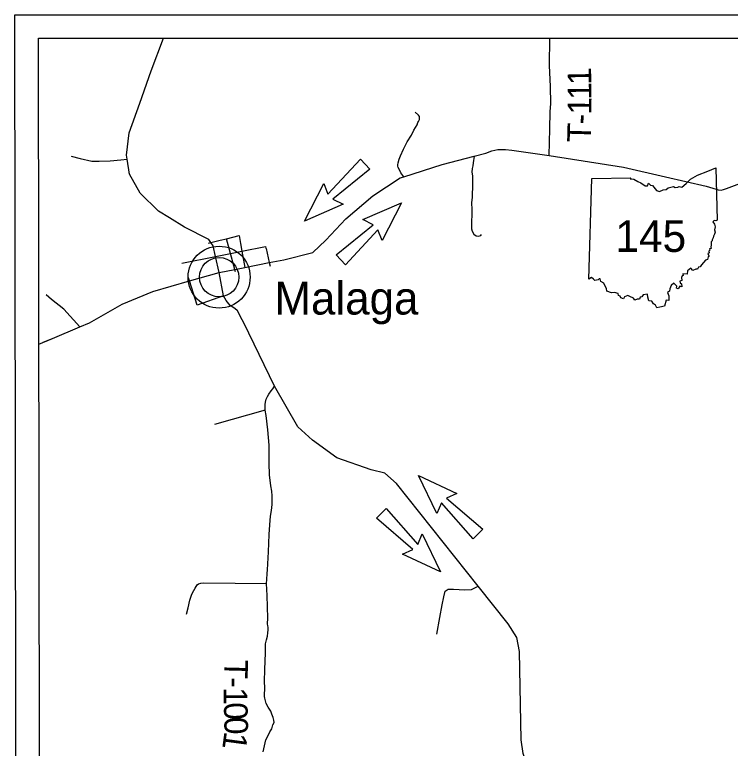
# Model space of a CAD drawing. Extents: x -15 to 405, y -40 to 87.
# Drawn here: x -14.941 to -13.126, y 40.321 to 42.183 of the extents above; entities that cross this region are included whole.
import ezdxf

# ---------------------------------------------------------------- set-up
doc = ezdxf.new("R2010")
doc.units = 0
for name, color, linetype in [('GM_P_State_Location', 7, 'Continuous'), ('GM_X_Major_River', 7, 'Continuous'), ('GM_X_Minor_River', 7, 'Continuous'), ('GM_X_State_Location', 7, 'Continuous'), ('GM_X_State_Shield', 7, 'Continuous'), ('GM_X_Township_ROW', 7, 'Continuous'), ('GM_X_Township_Subdivision_Text', 7, 'Continuous'), ('GM_X_Township_Text', 7, 'Continuous')]:
    doc.layers.add(name, color=color, linetype=linetype)

msp = doc.modelspace()

# ---------------------------------------------------------------- linework, layer by layer
at = {"layer": 'GM_P_State_Location'}
for points in [[(-13.5861, 41.8249), (-13.5843, 41.893), (-13.5829, 41.9364), (-13.5815, 41.9568), (-13.5828, 42.0002), (-13.5847, 42.0539), (-13.5845, 42.1225)], [(-13.9544, 41.7714), (-13.962, 41.7816), (-13.9657, 41.7884), (-13.9687, 41.7945), (-13.9699, 41.798), (-13.9695, 41.8012), (-13.9684, 41.8068), (-13.9665, 41.8161), (-13.963, 41.8245), (-13.9551, 41.8411), (-13.9457, 41.8597), (-13.9351, 41.8766), (-13.9292, 41.8895), (-13.9205, 41.9033), (-13.9186, 41.9093), (-13.917, 41.9117), (-13.9147, 41.9162), (-13.9148, 41.9242), (-13.9172, 41.9278), (-13.9257, 41.9353)], [(-13.7759, 41.8235), (-13.7784, 41.807), (-13.7792, 41.7993), (-13.7807, 41.7921), (-13.7818, 41.7829), (-13.7804, 41.7732), (-13.7803, 41.7612), (-13.7802, 41.7536), (-13.7801, 41.7407), (-13.7807, 41.7311), (-13.7814, 41.7191), (-13.7824, 41.705), (-13.7818, 41.6882), (-13.7817, 41.6741), (-13.7827, 41.6589), (-13.7826, 41.6508), (-13.7825, 41.6436), (-13.7824, 41.6392), (-13.7812, 41.6328), (-13.7771, 41.626), (-13.771, 41.6217), (-13.765, 41.6205), (-13.7594, 41.6222), (-13.7574, 41.6246)], [(-14.3073, 40.4798), (-14.3074, 40.4855), (-14.3074, 40.4905), (-14.3066, 40.5214), (-14.3051, 40.5631), (-14.305, 40.5864), (-14.3031, 40.5965), (-14.3004, 40.6057), (-14.2993, 40.6138), (-14.2982, 40.6218), (-14.2987, 40.6282), (-14.2991, 40.6322), (-14.3, 40.637), (-14.2997, 40.6511), (-14.3012, 40.7084), (-14.3024, 40.7393), (-14.3021, 40.749), (-14.3011, 40.7642), (-14.3, 40.7743), (-14.2978, 40.8192), (-14.2959, 40.8634), (-14.2946, 40.8883), (-14.2924, 40.9104), (-14.2898, 40.9241), (-14.2884, 40.9397), (-14.2881, 40.951), (-14.2886, 40.9618), (-14.2896, 40.9738), (-14.2917, 40.9874), (-14.2949, 41.0147), (-14.2961, 41.0448), (-14.2962, 41.0905), (-14.2991, 41.1294), (-14.3039, 41.1651), (-14.3065, 41.1791), (-14.3057, 41.1803), (-14.3062, 41.1871), (-14.3063, 41.1931), (-14.3055, 41.1996), (-14.3032, 41.2072), (-14.3005, 41.2137), (-14.297, 41.2197), (-14.291, 41.2282), (-14.2867, 41.2331), (-14.2821, 41.2396)], [(-14.2959, 41.0404), (-14.2961, 41.0448), (-14.2962, 41.0905), (-14.2991, 41.1294), (-14.3039, 41.1651), (-14.3065, 41.1791), (-14.3057, 41.1803), (-14.3062, 41.1871), (-14.3063, 41.1931), (-14.3055, 41.1996), (-14.3032, 41.2072), (-14.3005, 41.2137), (-14.297, 41.2197), (-14.291, 41.2282), (-14.2867, 41.2331), (-14.2821, 41.2396)], [(-14.3065, 41.1791), (-14.4349, 41.1423)], [(-14.3065, 41.1791), (-14.4349, 41.1423)], [(-14.5058, 40.6612), (-14.5016, 40.6777), (-14.497, 40.6966), (-14.4924, 40.7123), (-14.4873, 40.7212), (-14.4837, 40.7273), (-14.481, 40.7317), (-14.4786, 40.7357), (-14.4755, 40.7386), (-14.4691, 40.7403), (-14.4618, 40.7407), (-14.3024, 40.7393)], [(-13.871, 40.6107), (-13.8628, 40.6526), (-13.8573, 40.6848), (-13.8533, 40.7057), (-13.8495, 40.7194), (-13.8423, 40.7247), (-13.8283, 40.7249), (-13.7993, 40.7234), (-13.7829, 40.7236), (-13.7658, 40.7327)], [(-14.3113, 40.3123), (-14.3064, 40.3352), (-14.3044, 40.3424), (-14.3005, 40.3505), (-14.2939, 40.363), (-14.2891, 40.3703), (-14.2864, 40.3804), (-14.2837, 40.3864), (-14.2838, 40.3924), (-14.2859, 40.3996), (-14.2888, 40.4076), (-14.2921, 40.4156), (-14.2982, 40.4256), (-14.3036, 40.4351), (-14.3056, 40.4419), (-14.3073, 40.4479), (-14.3078, 40.4527), (-14.3078, 40.4576), (-14.3072, 40.4716), (-14.3073, 40.4798)]]:
    msp.add_lwpolyline(points, dxfattribs=at)
at = {"layer": 'GM_X_Major_River'}
for points in [[(-14.7983, 41.8235), (-14.7751, 41.8173), (-14.7456, 41.811), (-14.727, 41.8112), (-14.6989, 41.8113), (-14.6719, 41.8143), (-14.6564, 41.8162)], [(-14.4499, 41.6031), (-14.4438, 41.6046), (-14.4199, 41.6104), (-14.4199, 41.6104)], [(-14.4499, 41.6031), (-14.4438, 41.6046), (-14.4199, 41.6104), (-14.4199, 41.6104)], [(-14.4199, 41.6104), (-14.4043, 41.6141), (-14.3719, 41.622), (-14.3684, 41.6022), (-14.3684, 41.602)], [(-14.4199, 41.6104), (-14.4043, 41.6141), (-14.3719, 41.622), (-14.3684, 41.6022), (-14.3684, 41.602)], [(-14.3814, 41.5296), (-14.3831, 41.536), (-14.3941, 41.5765), (-14.4043, 41.6141)], [(-14.3814, 41.5296), (-14.3831, 41.536), (-14.3941, 41.5765), (-14.4043, 41.6141)], [(-14.5174, 41.5516), (-14.4319, 41.5689), (-14.3941, 41.5765), (-14.365, 41.5824), (-14.3051, 41.5945), (-14.304, 41.5894)], [(-14.5174, 41.5516), (-14.4319, 41.5689), (-14.3941, 41.5765), (-14.365, 41.5824), (-14.3051, 41.5945), (-14.304, 41.5894)], [(-14.3684, 41.602), (-14.365, 41.5824), (-14.3577, 41.5411)], [(-14.3684, 41.602), (-14.365, 41.5824), (-14.3577, 41.5411)], [(-14.304, 41.5894), (-14.3039, 41.5891), (-14.2957, 41.5533), (-14.2936, 41.5444)], [(-14.304, 41.5894), (-14.3039, 41.5891), (-14.2957, 41.5533), (-14.2936, 41.5444)], [(-14.4115, 41.4691), (-14.4783, 41.4453), (-14.498, 41.5069), (-14.5005, 41.5145)], [(-14.4115, 41.4691), (-14.4783, 41.4453), (-14.498, 41.5069), (-14.5005, 41.5145)]]:
    msp.add_lwpolyline(points, dxfattribs=at)
at = {"layer": 'GM_X_State_Location'}
for p, q in [((-14.8692, 34.0644), (-14.8813, 42.1225)), ((-14.8813, 42.1225), (-5.8856, 42.1225)), ((-14.1468, 41.7269), (-14.0643, 41.8156)), ((-14.0643, 41.8156), (-14.0408, 41.7905)), ((-14.0408, 41.7905), (-14.1349, 41.7141)), ((-14.2066, 41.6588), (-14.1577, 41.754)), ((-14.1577, 41.754), (-14.1468, 41.7269)), ((-13.4851, 41.5118), (-13.478, 41.7671)), ((-14.1084, 41.7013), (-14.2066, 41.6588)), ((-14.1349, 41.7141), (-14.1084, 41.7013)), ((-14.0585, 41.6624), (-13.9604, 41.7048)), ((-13.9604, 41.7048), (-14.0091, 41.6095)), ((-14.032, 41.6494), (-14.0585, 41.6624)), ((-14.1261, 41.573), (-14.032, 41.6494)), ((-14.0201, 41.6367), (-14.1025, 41.5479)), ((-14.0091, 41.6095), (-14.0201, 41.6367)), ((-14.1025, 41.5479), (-14.1261, 41.573)), ((-13.917, 41.0129), (-13.8198, 40.968)), ((-13.8706, 40.9166), (-13.917, 41.0129)), ((-13.8198, 40.968), (-13.8465, 40.9559)), ((-13.8465, 40.9559), (-13.7544, 40.8771)), ((-13.8587, 40.9435), (-13.8706, 40.9166)), ((-13.7786, 40.8526), (-13.8587, 40.9435)), ((-14.0235, 40.9046), (-13.9994, 40.9291)), ((-13.9994, 40.9291), (-13.9192, 40.8381)), ((-13.9315, 40.8258), (-14.0235, 40.9046)), ((-13.9192, 40.8381), (-13.9075, 40.8651)), ((-13.9075, 40.8651), (-13.8611, 40.7687)), ((-13.7544, 40.8771), (-13.7786, 40.8526)), ((-13.9582, 40.8137), (-13.9315, 40.8258)), ((-13.8611, 40.7687), (-13.9582, 40.8137))]:
    msp.add_line(p, q, dxfattribs=at)
msp.add_lwpolyline([(-14.9291, 34.0044), (-14.9414, 42.1825), (-5.8257, 42.1825), (-5.8134, 34.0044)], close=True, dxfattribs=at)
for points in [[(-14.5486, 41.667), (-14.5765, 41.6841), (-14.6235, 41.7296), (-14.6501, 41.7775), (-14.6564, 41.8162), (-14.658, 41.8259), (-14.6511, 41.883), (-14.6244, 41.9579), (-14.595, 42.0397), (-14.5638, 42.1225)], [(-14.4224, 41.5283), (-14.3831, 41.536), (-14.3577, 41.5411), (-14.2957, 41.5533), (-14.2585, 41.5607), (-14.1852, 41.5789), (-14.1521, 41.61), (-14.1019, 41.6645), (-14.0333, 41.7227), (-13.9634, 41.7685), (-13.9544, 41.7714), (-13.8573, 41.8026), (-13.7759, 41.8235), (-13.7467, 41.831), (-13.7311, 41.8368), (-13.7159, 41.84), (-13.6966, 41.8402), (-13.6805, 41.8391), (-13.5861, 41.8249), (-13.3972, 41.7958), (-13.2906, 41.7709), (-13.1872, 41.7471), (-13.1624, 41.7396), (-13.1572, 41.7383), (-13.1496, 41.7374), (-13.1436, 41.7386), (-13.1364, 41.7411), (-13.0545, 41.7719)], [(-13.478, 41.7671), (-13.3789, 41.7687), (-13.3805, 41.7656), (-13.3712, 41.765), (-13.3612, 41.7596), (-13.3529, 41.7561), (-13.3426, 41.748), (-13.3364, 41.7481), (-13.3338, 41.7547), (-13.3291, 41.7496), (-13.3235, 41.7487), (-13.3139, 41.7364), (-13.3059, 41.7338), (-13.2963, 41.738), (-13.2892, 41.7387), (-13.284, 41.7428), (-13.2704, 41.7464), (-13.2666, 41.7442), (-13.2594, 41.7447), (-13.2558, 41.7462), (-13.2495, 41.7448), (-13.2385, 41.7541), (-13.2271, 41.7651), (-13.2096, 41.7754), (-13.1835, 41.7852), (-13.1628, 41.7939), (-13.1599, 41.6614)], [(-14.5486, 41.667), (-14.5765, 41.6841), (-14.6235, 41.7296), (-14.6501, 41.7775), (-14.6508, 41.7814)], [(-14.4224, 41.5283), (-14.4319, 41.5689), (-14.4381, 41.5956), (-14.4438, 41.6046), (-14.4487, 41.6123), (-14.5103, 41.6436), (-14.5486, 41.667)], [(-14.4224, 41.5283), (-14.4319, 41.5689), (-14.4381, 41.5956), (-14.4438, 41.6046), (-14.4487, 41.6123), (-14.5103, 41.6436), (-14.5486, 41.667)], [(-13.1599, 41.6614), (-13.1629, 41.6596), (-13.1676, 41.6605), (-13.1708, 41.6568), (-13.1668, 41.6506), (-13.165, 41.644), (-13.1667, 41.6368), (-13.165, 41.6308), (-13.1661, 41.6259), (-13.1691, 41.6209), (-13.1701, 41.6162), (-13.1727, 41.6112), (-13.1725, 41.6084), (-13.1749, 41.6062), (-13.1745, 41.5979), (-13.1757, 41.5933), (-13.1752, 41.5894), (-13.1792, 41.5883), (-13.1783, 41.585), (-13.1808, 41.5825), (-13.1802, 41.5782), (-13.1831, 41.5754), (-13.1804, 41.5698), (-13.1825, 41.5681), (-13.1844, 41.5613), (-13.1894, 41.5599), (-13.1995, 41.5476), (-13.203, 41.5429), (-13.207, 41.5417), (-13.2092, 41.5369), (-13.2141, 41.5369), (-13.2216, 41.5336), (-13.2264, 41.5393), (-13.2348, 41.5324), (-13.2358, 41.5245), (-13.2464, 41.5247), (-13.246, 41.5207), (-13.2484, 41.5195), (-13.2505, 41.5155), (-13.2493, 41.5083), (-13.2543, 41.5065), (-13.2537, 41.5023), (-13.2505, 41.4998), (-13.2491, 41.4919), (-13.2544, 41.4934), (-13.2587, 41.4867), (-13.2632, 41.4883), (-13.2617, 41.494), (-13.2693, 41.5009), (-13.2764, 41.4954), (-13.2801, 41.4866), (-13.2802, 41.4807), (-13.2855, 41.4772), (-13.2821, 41.4689), (-13.2827, 41.4632), (-13.2826, 41.4577), (-13.2892, 41.458), (-13.2933, 41.4433)], [(-14.8802, 41.3469), (-14.8451, 41.3608), (-14.7762, 41.3901), (-14.7518, 41.4004), (-14.6691, 41.4479), (-14.5911, 41.4805), (-14.498, 41.5069), (-14.4224, 41.5283)], [(-14.8692, 41.3512), (-14.8451, 41.3608), (-14.7762, 41.3901), (-14.7518, 41.4004), (-14.6691, 41.4479), (-14.5911, 41.4805), (-14.498, 41.5069), (-14.4224, 41.5283)], [(-14.3606, 41.4004), (-14.3645, 41.4083), (-14.3763, 41.4307), (-14.383, 41.4367), (-14.3949, 41.4442), (-14.4052, 41.4569), (-14.4115, 41.4691), (-14.4224, 41.5283)], [(-14.3606, 41.4004), (-14.3645, 41.4083), (-14.3763, 41.4307), (-14.383, 41.4367), (-14.3949, 41.4442), (-14.4052, 41.4569), (-14.4115, 41.4691), (-14.4224, 41.5283)], [(-13.2933, 41.4433), (-13.3049, 41.4405), (-13.3128, 41.4388), (-13.3157, 41.4454), (-13.3214, 41.449), (-13.3252, 41.4557), (-13.3334, 41.4566), (-13.3353, 41.4658), (-13.3362, 41.4732), (-13.3476, 41.4714), (-13.3506, 41.4669), (-13.3546, 41.4656), (-13.3569, 41.461), (-13.3624, 41.4607), (-13.3682, 41.4585), (-13.3721, 41.463), (-13.3816, 41.4675), (-13.3859, 41.4698), (-13.3949, 41.4663), (-13.3969, 41.4619), (-13.404, 41.4638), (-13.4057, 41.4686), (-13.41, 41.4701), (-13.411, 41.4751), (-13.4202, 41.4779), (-13.4274, 41.4768), (-13.4398, 41.4808), (-13.4406, 41.4875), (-13.4449, 41.4957), (-13.4471, 41.5013), (-13.455, 41.5057), (-13.4566, 41.5124), (-13.4591, 41.5122), (-13.4614, 41.5095), (-13.4702, 41.5082), (-13.4737, 41.511), (-13.4786, 41.5157), (-13.4851, 41.5118)], [(-13.4329, 39.7018), (-13.4346, 39.726), (-13.4357, 39.7581), (-13.4532, 39.7868), (-13.4962, 39.8511), (-13.5455, 39.9354), (-13.566, 39.9955), (-13.6019, 40.1272), (-13.6371, 40.2666), (-13.6519, 40.3078), (-13.657, 40.3427), (-13.6611, 40.5665), (-13.6674, 40.6025), (-13.6894, 40.6369), (-13.7658, 40.7327), (-13.9731, 40.9927), (-14.0022, 41.0194), (-14.0372, 41.028), (-14.1246, 41.0582), (-14.1859, 41.1031), (-14.2231, 41.137), (-14.2821, 41.2396), (-14.3606, 41.4004)]]:
    msp.add_lwpolyline(points, dxfattribs=at)
at = {"layer": 'GM_X_Township_Subdivision_Text'}
for radius in [0.0786, 0.0786, 0.0498, 0.0498]:
    msp.add_circle((-14.4228, 41.5165), radius, dxfattribs=at)
at = {"layer": 'GM_X_Township_Text'}
msp.add_lwpolyline([(-14.7762, 41.3901), (-14.8168, 41.435), (-14.848, 41.46), (-14.8616, 41.4713)], dxfattribs=at)

# ---------------------------------------------------------------- texts
at = {"layer": 'GM_X_Minor_River'}
for s, rotation, p in [('1', 91.1603, (-13.4787, 42.0046)), ('1', 90.5013, (-13.4784, 41.9669)), ('1', 89.5897, (-13.4787, 41.9289)), ('-', 88.8071, (-13.4792, 41.9034)), ('T', 88.4699, (-13.4804, 41.8581)), ('T', 268.4785, (-14.4093, 40.547)), ('-', 268.5413, (-14.4105, 40.5021)), ('1', 270.0701, (-14.4111, 40.4757)), ('0', 271.7229, (-14.4111, 40.4368)), ('0', 271.1137, (-14.41, 40.4001)), ('1', 262.4167, (-14.4091, 40.3655))]:
    msp.add_text(s, height=0.06, rotation=rotation, dxfattribs=at).set_placement(p)
at = {"layer": 'GM_X_State_Shield'}
msp.add_text('145', height=0.08048, dxfattribs=at).set_placement((-13.4179, 41.5805))
at = {"layer": 'GM_X_Township_ROW'}
msp.add_text('Malaga', height=0.08333, rotation=0, dxfattribs=at).set_placement((-14.2827, 41.4217))

doc.saveas('drawing.dxf')
